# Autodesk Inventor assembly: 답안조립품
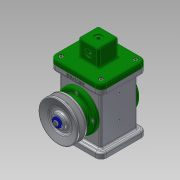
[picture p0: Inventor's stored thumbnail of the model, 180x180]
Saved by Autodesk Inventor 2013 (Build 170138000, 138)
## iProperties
Created: 2017-08
Part Number: 답안조립품
Document SubType Name: Assembly
Designer: cad14
Author: cad14
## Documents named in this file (18)
- C:\Documents and Settings\cad14\바탕 화면\470808V1010\답안조립품.iam
- C:\Documents and Settings\cad14\바탕 화면\470808V1010\1.본체.ipt
- C:\Documents and Settings\cad14\바탕 화면\470808V1010\덮개.ipt
- C:\Documents and Settings\cad14\바탕 화면\470808V1010\앞커버.ipt
- C:\Documents and Settings\cad14\바탕 화면\470808V1010\뒤커버.ipt
- C:\Documents and Settings\cad14\바탕 화면\470808V1010\베어링 17 x 40 x 12.ipt
- C:\Documents and Settings\cad14\바탕 화면\470808V1010\편심축.ipt
- C:\Documents and Settings\cad14\바탕 화면\470808V1010\볼트 M4 x 8.ipt
- C:\Documents and Settings\cad14\바탕 화면\470808V1010\오일 실 17 30 8.ipt
- C:\Documents and Settings\cad14\바탕 화면\470808V1010\키 4 x 4 x 12.ipt
- C:\Documents and Settings\cad14\바탕 화면\470808V1010\V-벨트풀리.ipt
- C:\Documents and Settings\cad14\바탕 화면\470808V1010\와셔 4x16.ipt
- C:\Documents and Settings\cad14\바탕 화면\470808V1010\볼트 M4 x 10.ipt
- C:\Documents and Settings\cad14\바탕 화면\470808V1010\슬라이더.ipt
- C:\Documents and Settings\cad14\바탕 화면\470808V1010\링크.ipt
- C:\Documents and Settings\cad14\바탕 화면\470808V1010\E-링.ipt
- C:\Documents and Settings\cad14\바탕 화면\470808V1010\클레비스 핀 6 x 22.ipt
- 클레비스 핀 6 x 22.ipt
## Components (3 placed, 3 different names)
1. 1.본체:1 — 각도:1
2. V-벨트풀리:1 — 각도:3
3. E-링:1
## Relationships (2: Angle 2)
- 각도:1 [Angle]: 1.본체:1
- 각도:3 [Angle]: V-벨트풀리:1
